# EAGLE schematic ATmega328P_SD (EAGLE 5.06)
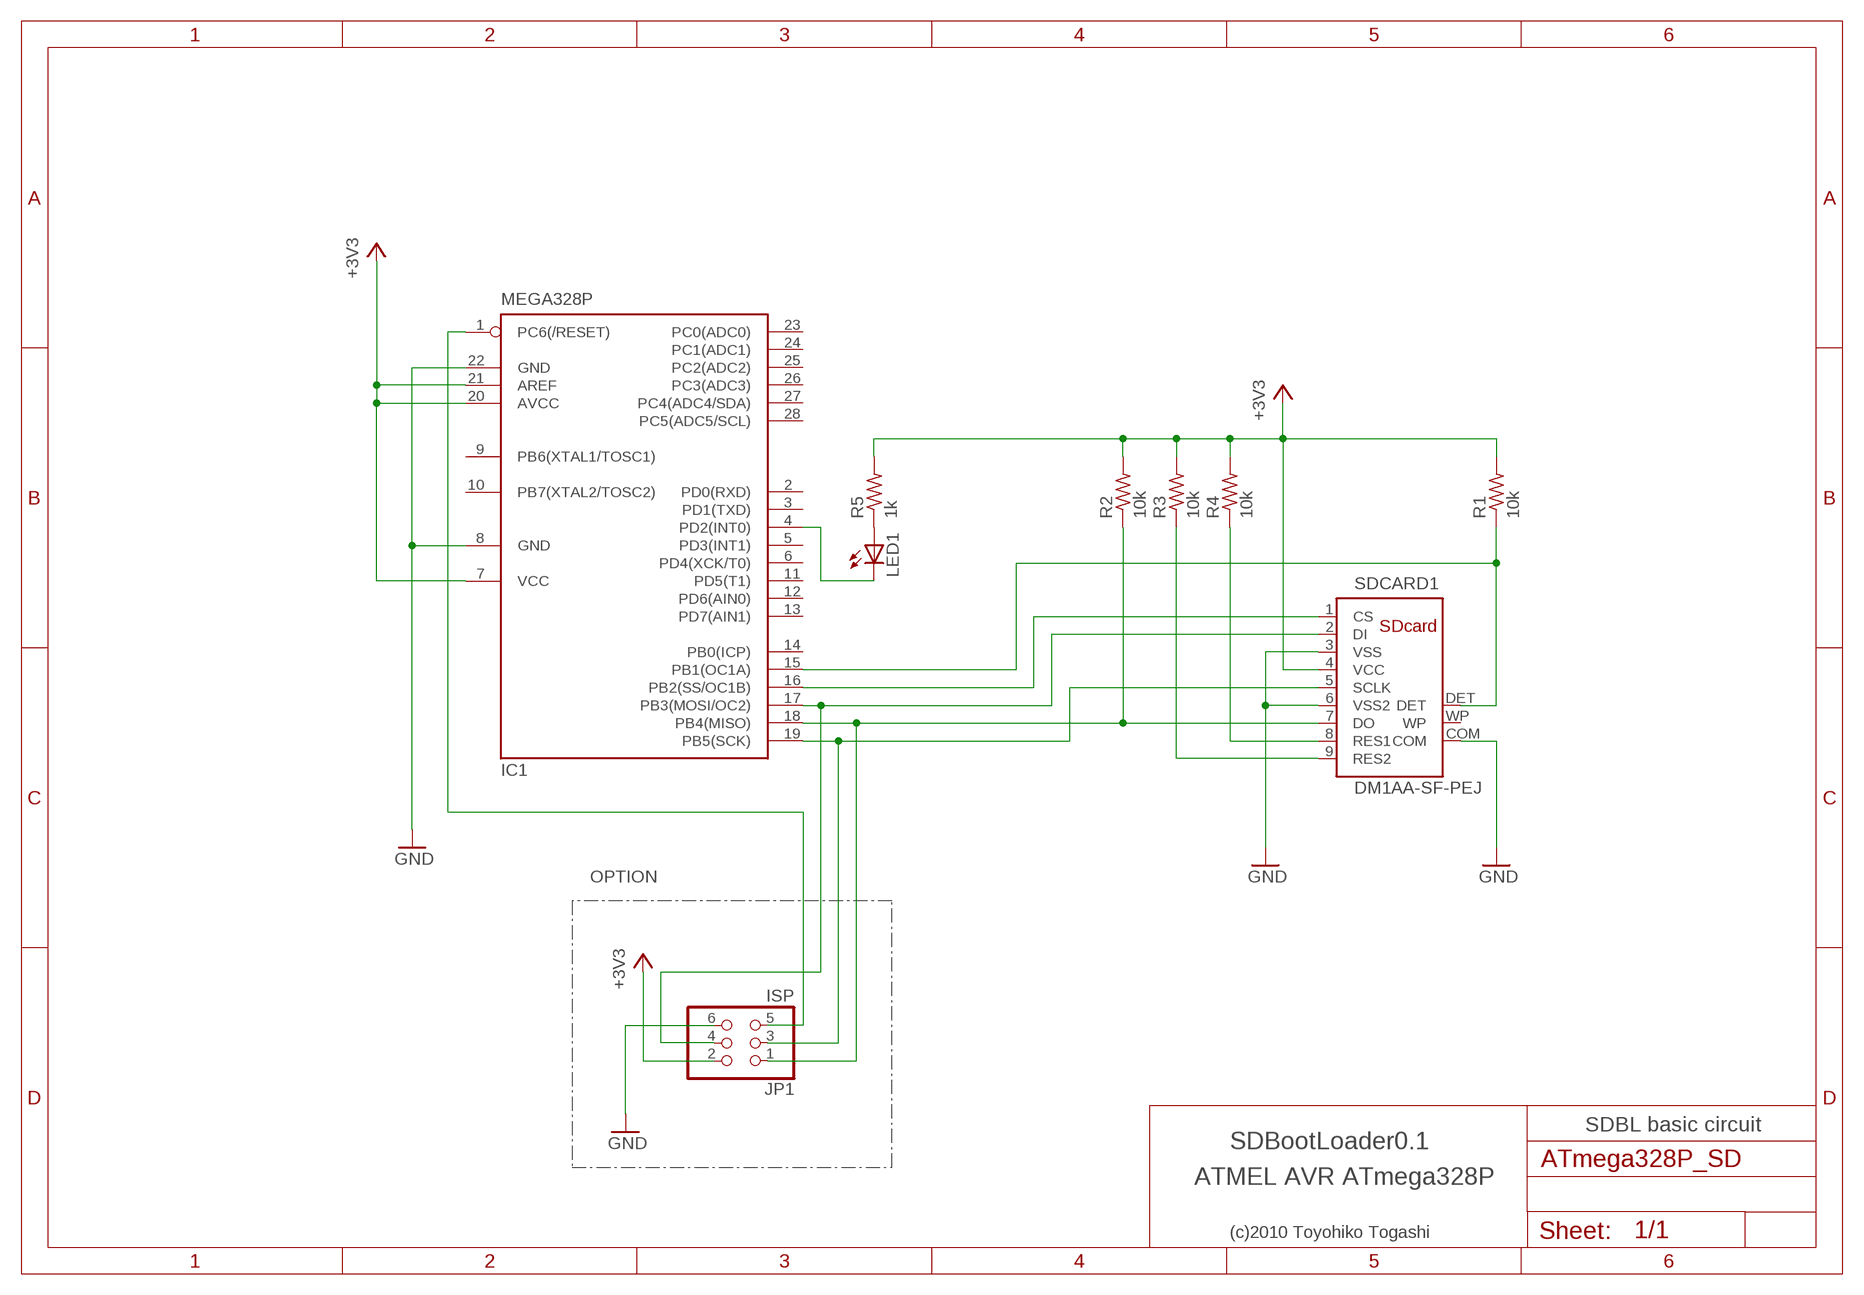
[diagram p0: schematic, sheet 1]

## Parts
IC1  MEGA328P  MEGA8-P  [DIL28-3]
JP1  ISP  PINHD-2X3  [2X03]
LED1  LED5MM  [LED5MM]
R1  10k  R-US_0204/5  [0204/5]
R2  10k  R-US_0204/5  [0204/5]
R3  10k  R-US_0204/5  [0204/5]
R4  10k  R-US_0204/5  [0204/5]
R5  1k  R-US_0204/5  [0204/5]
SDCARD1  DM1AA-SF-PEJ  [DM1AA]

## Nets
+3V3: IC1.7(VCC) IC1.20(AVCC) IC1.21(AREF) JP1.2 R1.2 R2.2 R3.2 R4.2 R5.2 SDCARD1.4(VCC)
GND: IC1.8(GND) IC1.22(GND) JP1.6 SDCARD1.3(VSS) SDCARD1.6(VSS2) SDCARD1.COM
N$1: LED1.A R5.1
N$2: IC1.16(PB2(SS/OC1B)) SDCARD1.1(CS)
N$3: IC1.17(PB3(MOSI/OC2)) JP1.4 SDCARD1.2(DI)
N$4: IC1.4(PD2(INT0)) LED1.K(C)
N$5: IC1.19(PB5(SCK)) JP1.3 SDCARD1.5(SCLK)
N$6: IC1.18(PB4(MISO)) JP1.1 R2.1 SDCARD1.7(DO)
N$7: R4.1 SDCARD1.8(RES1)
N$8: R3.1 SDCARD1.9(RES2)
N$9: IC1.1(PC6(/RESET)) JP1.5
N$10: IC1.15(PB1(OC1A)) R1.1 SDCARD1.DET
Unconnected: IC1.2(PD0(RXD)) IC1.3(PD1(TXD)) IC1.5(PD3(INT1)) IC1.6(PD4(XCK/T0)) IC1.9(PB6(XTAL1/TOSC1)) IC1.10(PB7(XTAL2/TOSC2)) IC1.11(PD5(T1)) IC1.12(PD6(AIN0)) IC1.13(PD7(AIN1)) IC1.14(PB0(ICP)) IC1.23(PC0(ADC0)) IC1.24(PC1(ADC1)) IC1.25(PC2(ADC2)) IC1.26(PC3(ADC3)) IC1.27(PC4(ADC4/SDA)) IC1.28(PC5(ADC5/SCL)) SDCARD1.WP

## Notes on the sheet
- OPTION
- SDBL basic circuit
- SDBootLoader0.1
- ATMEL AVR ATmega328P
- (c)2010 Toyohiko Togashi

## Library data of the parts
IC1 = atmel:MEGA8-P: MICROCONTROLLER 8 Kbytes FLASH, 1 kbytes SRAM, 512 bytes EEPROM, USART, 4-channel 10 bit ADC, 2-channel 8 bit ADC Pin compatible with Atmega48, ATMega88, ATMega168 Source: avr.lbr
JP1 = pinhead:PINHD-2X3: PIN HEADER
LED1 = led:LED: LED
R1-R5 = rcl:R-US_: RESISTOR, American symbol
SDCARD1 = TOG:DM1AA-SF-PEJ: SDcard connector HIROSE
